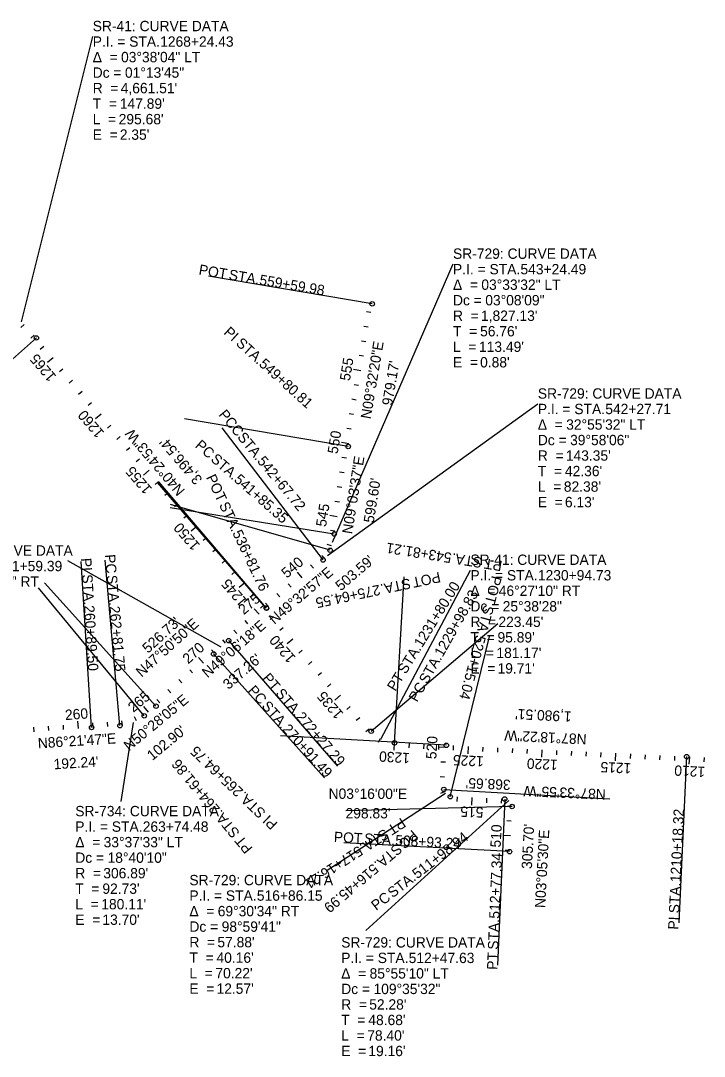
# Model space of a CAD drawing. Extents: x 99589 to 110840, y 526591 to 533644.
# Drawn here: x 102357 to 106985, y 526635 to 533644 of the extents above; entities that cross this region are included whole.
import ezdxf

# ---------------------------------------------------------------- set-up
doc = ezdxf.new("R2010")
doc.units = 0
for name, color, linetype in [('GE_P_Alignment_500_Bearings', 7, 'Continuous'), ('GE_P_Alignment_500_Cardinal_Points', 7, 'Continuous'), ('GE_P_Alignment_500_Curve_Data', 7, 'Continuous'), ('GE_P_Alignment_500_Distances', 7, 'Continuous'), ('GE_P_Alignment_500_Stations', 7, 'Continuous')]:
    doc.layers.add(name, color=color, linetype=linetype)

msp = doc.modelspace()

# ---------------------------------------------------------------- linework, layer by layer
at = {"layer": 'GE_P_Alignment_500_Cardinal_Points'}
for p, q in [((104736.9, 531727.6), (103627.4, 531914)), ((102463.2, 531497.2), (101620.2, 530752.1)), ((104574.6, 530762), (103465.2, 530948.4)), ((104404.3, 529994.3), (103720.9, 530887.8)), ((104019.9, 529668.9), (103283.4, 530519.3)), ((104021.1, 529667.5), (103291.2, 530523.6)), ((104452.2, 530059.9), (103371, 530370.7)), ((104480.2, 530169.9), (103369.2, 530347)), ((102836.9, 528860.6), (102765.5, 529983.3)), ((103028.8, 528872.8), (102928.3, 529993.3)), ((104887.7, 528756.3), (104952.6, 529879.4)), ((103272.8, 529004.6), (102517.8, 529838.6)), ((103193.4, 528939.1), (102477.4, 529806.8)), ((104730, 528835), (105586.6, 529564.4)), ((105265.5, 528391.9), (105534.3, 529484.3)), ((103765, 529448.1), (104501.5, 528597.7)), ((103663.3, 529358.1), (104414.2, 528520.4)), ((105238.8, 528739.8), (104115.7, 528803.9)), ((106866, 528663.2), (106813.1, 527539.4)), ((105221.8, 528441.4), (106345, 528377.3)), ((105633.8, 528376.3), (105586, 527252.3)), ((105683.7, 528325.4), (104559.1, 528295.4)), ((105667.2, 528020.2), (104543.9, 528080.8))]:
    msp.add_line(p, q, dxfattribs=at)
for centre in [(104736.9, 531727.6), (102463.2, 531497.2), (104574.6, 530762), (104480.2, 530169.9), (104452.2, 530059.9), (104404.3, 529994.3), (104019.9, 529668.9), (104021.1, 529667.5), (103765, 529448.1), (103663.3, 529358.1), (103272.8, 529004.6), (103193.4, 528939.1), (102836.9, 528860.6), (103028.8, 528872.8), (104730, 528835), (104887.7, 528756.3), (105238.8, 528739.8), (106866, 528663.2), (105221.8, 528441.4), (105265.5, 528391.9), (105633.8, 528376.3), (105683.7, 528325.4), (105667.2, 528020.2)]:
    msp.add_circle(centre, 15, dxfattribs=at)
at = {"layer": 'GE_P_Alignment_500_Curve_Data'}
for p, q in [((102363.5, 531606.4), (102844.5, 533538)), ((104467.1, 530114.7), (105284, 531997.5)), ((104433.3, 530024.8), (105858.3, 531051.1)), ((103714, 529403.3), (102676.4, 529987.7)), ((104796.1, 528781.9), (105401.9, 529925.8)), ((103118.5, 528894.8), (103035.2, 528360)), ((105233.2, 528414.1), (104425.4, 527888.7)), ((105660.9, 528366), (104694.1, 527486.6))]:
    msp.add_line(p, q, dxfattribs=at)
at = {"layer": 'GE_P_Alignment_500_Stations'}
for p, q in [((104726.9, 531668.5), (104697.3, 531673.4)), ((102380.2, 531588.6), (102358.2, 531568.1)), ((104710.4, 531569.8), (104680.8, 531574.8)), ((102447.6, 531514.7), (102425.2, 531494.7)), ((102512.8, 531438.9), (102489.9, 531419.5)), ((104693.8, 531471.2), (104664.2, 531476.2)), ((102577.6, 531362.8), (102539.5, 531330.4)), ((104677.2, 531372.6), (104647.6, 531377.6)), ((102642.4, 531286.6), (102619.6, 531267.2)), ((104660.6, 531274), (104611.3, 531282.3)), ((102707.3, 531210.5), (102684.4, 531191)), ((104644.1, 531175.4), (104614.5, 531180.3)), ((102772.1, 531134.4), (102749.3, 531114.9)), ((104627.5, 531076.7), (104597.9, 531081.7)), ((102836.9, 531058.2), (102814.1, 531038.8)), ((102901.8, 530982.1), (102863.7, 530949.7)), ((104610.9, 530978.1), (104581.3, 530983.1)), ((102966.6, 530905.9), (102943.8, 530886.5)), ((104594.4, 530879.5), (104564.8, 530884.5)), ((103031.4, 530829.8), (103008.6, 530810.4)), ((103096.3, 530753.7), (103073.4, 530734.2)), ((104577.8, 530780.9), (104528.5, 530789.2)), ((103161.1, 530677.5), (103138.3, 530658.1)), ((104561.9, 530682.2), (104532.3, 530686.9)), ((103225.9, 530601.4), (103187.9, 530569)), ((104546.1, 530583.4), (104516.5, 530588.1)), ((103290.8, 530525.3), (103267.9, 530505.8)), ((103355.6, 530449.1), (103332.7, 530429.7)), ((104530.4, 530484.7), (104500.8, 530489.4)), ((103420.4, 530373), (103397.6, 530353.5)), ((104514.6, 530385.9), (104485, 530390.6)), ((103485.3, 530296.8), (103462.4, 530277.4)), ((104498.9, 530287.2), (104449.5, 530295)), ((103550.1, 530220.7), (103512, 530188.3)), ((104483.1, 530188.4), (104453.5, 530193.1)), ((103614.9, 530144.6), (103592.1, 530125.1)), ((104460.9, 530091), (104431.9, 530098.8)), ((103679.7, 530068.4), (103656.9, 530049)), ((104415.5, 530003.7), (104394.9, 530025.6)), ((103744.6, 529992.3), (103721.7, 529972.8)), ((104339.4, 529938.9), (104319.9, 529961.7)), ((103809.4, 529916.2), (103786.6, 529896.7)), ((104263.3, 529874), (104230.9, 529912.1)), ((103874.2, 529840), (103836.2, 529807.6)), ((104187.2, 529809.1), (104167.7, 529832)), ((103939.1, 529763.9), (103916.2, 529744.4)), ((104111.1, 529744.2), (104091.6, 529767.1)), ((104003.9, 529687.8), (103981.1, 529668.3)), ((104035, 529679.4), (104015.5, 529702.2)), ((103971.1, 529626.7), (103938.4, 529664.4)), ((104068.7, 529611.6), (104045.9, 529592.2)), ((103895.6, 529561.2), (103875.9, 529583.9)), ((104133.6, 529535.5), (104110.7, 529516)), ((103820, 529495.7), (103800.3, 529518.4)), ((104198.4, 529459.3), (104160.3, 529426.9)), ((103744.5, 529430.1), (103724.7, 529452.7)), ((103595.5, 529296.7), (103561.9, 529333.8)), ((103669.6, 529363.8), (103649.6, 529386.2)), ((104263.2, 529383.2), (104240.4, 529363.8)), ((103521.3, 529229.6), (103501.2, 529251.8)), ((104328.1, 529307.1), (104305.2, 529287.6)), ((103447.2, 529162.5), (103427.1, 529184.7)), ((104392.9, 529230.9), (104370.1, 529211.5)), ((103373.1, 529095.4), (103352.9, 529117.6)), ((104457.7, 529154.8), (104434.9, 529135.3)), ((103298.9, 529028.3), (103278.8, 529050.5)), ((104522.6, 529078.7), (104484.5, 529046.2)), ((103222.9, 528963.4), (103191, 529002)), ((104587.4, 529002.5), (104564.5, 528983.1)), ((102747.7, 528854), (102744, 528903.9)), ((102947.2, 528867.6), (102945.3, 528897.6)), ((103046.9, 528875), (103042.4, 528904.6)), ((103141.6, 528905.5), (103127.9, 528932.2)), ((104652.2, 528926.4), (104629.4, 528906.9)), ((102448.5, 528831.9), (102446.3, 528861.8)), ((102548.2, 528839.3), (102546, 528869.2)), ((102647.9, 528846.6), (102645.7, 528876.5)), ((102847.4, 528861.3), (102845.5, 528891.2)), ((104717.1, 528850.2), (104694.2, 528830.8)), ((104791.4, 528784.4), (104776.8, 528758.2)), ((104886.5, 528756.3), (104883.4, 528706.4)), ((104986.4, 528751.6), (104985, 528721.7)), ((105086.3, 528746.9), (105084.9, 528717)), ((105186.2, 528742.2), (105184.8, 528712.3)), ((105238, 528724.7), (105188.1, 528727.6)), ((105286.1, 528737.5), (105284.7, 528707.6)), ((105386, 528732.8), (105383.6, 528682.9)), ((105485.9, 528728.1), (105484.5, 528698.2)), ((105585.8, 528723.4), (105584.4, 528693.5)), ((105685.7, 528718.7), (105684.2, 528688.8)), ((105785.5, 528714), (105784.1, 528684.1)), ((105885.4, 528709.3), (105883.1, 528659.4)), ((105985.3, 528704.6), (105983.9, 528674.7)), ((106085.2, 528699.9), (106083.8, 528670)), ((106185.1, 528695.2), (106183.7, 528665.3)), ((106285, 528690.5), (106283.6, 528660.6)), ((105232.3, 528624.9), (105202.3, 528626.6)), ((106384.9, 528685.8), (106382.5, 528635.9)), ((106484.8, 528681.1), (106483.4, 528651.2)), ((106584.7, 528676.4), (106583.2, 528646.5)), ((106684.5, 528671.7), (106683.1, 528641.8)), ((106784.4, 528667), (106783, 528637.1)), ((106884.3, 528662.2), (106881.7, 528612.3)), ((106984.2, 528657), (106982.6, 528627)), ((105226.6, 528525.1), (105196.6, 528526.8)), ((105225.9, 528425.8), (105198.2, 528414.2)), ((105311.4, 528390), (105310.2, 528360)), ((105411.3, 528385.7), (105409.2, 528335.8)), ((105511.2, 528381.5), (105510, 528351.5)), ((105611.2, 528377.2), (105609.9, 528347.3)), ((105683.7, 528326.5), (105653.7, 528325.1)), ((105678.4, 528226.6), (105648.4, 528228.2)), ((105673, 528126.8), (105623.1, 528129.5)), ((105667.6, 528026.9), (105637.7, 528028.5))]:
    msp.add_line(p, q, dxfattribs=at)

# ---------------------------------------------------------------- texts
at = {"layer": 'GE_P_Alignment_500_Bearings'}
for s, rotation, p in [('N09°32\'20"E', 80.46122, (104727, 530944.8)), ('N40°24\'53"W', 130.41474, (103473.3, 530466)), ('N09°03\'37"E', 80.93973, (104601.2, 530166.5)), ('N49°32\'57"E', 40.45073, (104074.4, 529555.3)), ('N47°50\'50"E', 42.15273, (103175.4, 529197.4)), ('N49°06\'18"E', 40.89492, (103621.8, 529192.8)), ('N50°28\'05"E', 39.53195, (103090.4, 528698.5)), ('N87°18\'22"W', 177.30607, (106190, 528815.1)), ('N86°21\'47"E', 3.63699, (102475, 528719)), ('N03°16\'00"E', 359.85197, (104441.7, 528377.6)), ('N87°33\'55"W', 177.56534, (106319.6, 528441.9)), ('N03°05\'30"E', 86.90826, (105907.7, 527637.4))]:
    msp.add_text(s, height=70, rotation=rotation, dxfattribs=at).set_placement(p)
at = {"layer": 'GE_P_Alignment_500_Cardinal_Points'}
for s, rotation, p in [('POT', 350.46122, (103558.9, 531926.6)), (' STA. ', 350.46122, (103736.4, 531896.8)), ('559+59.98', 350.46122, (103969.4, 531857.6)), ('PI', 317.95547, (103726.9, 531527.9)), (' STA. ', 317.95547, (103789.9, 531471.1)), ('549+80.81', 317.95547, (103965.3, 531312.8)), ('PCC', 309.6937, (103693.4, 530975.8)), ('PC', 318.68084, (103532.9, 530761.7)), (' STA. ', 309.6937, (103803.4, 530843.2)), (' STA. ', 318.68084, (103619, 530686.1)), ('542+67.72', 309.6937, (103954.3, 530661.4)), ('POT', 295.3785, (103609.9, 530553.6)), ('541+85.35', 318.68084, (103796.5, 530530.1)), (' STA. ', 295.3785, (103687, 530391)), ('536+81.76', 295.3785, (103788.3, 530177.5)), ('543+81.21', 170.93973, (105278.5, 530041.5)), ('PC', 275.12547, (102926.1, 530029.5)), (' STA. ', 170.93973, (105511.9, 530004.3)), ('PI', 273.63699, (102765.2, 530005.7)), ('PT', 170.93973, (105620.8, 529986.9)), (' STA. ', 273.63699, (102770.6, 529921.1)), (' STA. ', 275.12547, (102936.3, 529915.3)), ('POT', 191.94192, (105191.2, 529913.9)), ('POT', 255.05541, (105547.5, 529892.2)), ('275+64.55', 191.94192, (104783.9, 529827.8)), (' STA. ', 191.94192, (105015.1, 529876.7)), ('1231+80.00', 58.3886, (105074.3, 529396.4)), ('1229+98.83', 60.45546, (105213.5, 529333.2)), ('260+89.50', 273.63699, (102785.5, 529685.3)), ('262+81.75', 275.12547, (102957.4, 529680)), (' STA. ', 255.05541, (105501.1, 529718.3)), ('520+15.04', 255.05541, (105440.2, 529490)), (' STA. ', 58.3886, (104950.5, 529195.2)), (' STA. ', 60.45546, (105097, 529127.7)), ('PT', 310.89492, (103988.7, 529191.4)), ('PT', 58.3886, (104892.6, 529101.2)), ('PC', 311.87124, (103890, 529106.8)), (' STA. ', 310.89492, (104061, 529108)), ('PC', 60.45546, (105040.5, 529027.9)), (' STA. ', 311.87124, (103966.5, 529021.5)), ('272+27.29', 310.89492, (104215.7, 528929.3)), ('270+91.49', 311.87124, (104124.2, 528845.5)), ('265+64.75', 136.35225, (103869.2, 528434.3)), ('264+61.86', 129.53195, (103710.6, 528310.8)), (' STA. ', 136.35225, (104040.2, 528271.2)), (' STA. ', 129.53195, (103861, 528128.6)), ('PI', 136.35225, (104101.5, 528212.7)), ('1210+18.32', 87.30607, (106824.9, 527811.7)), ('PT', 213.07385, (104933.5, 528252.4)), ('POT', 356.90826, (104475.9, 528085.6)), (' STA. ', 213.07385, (104841, 528192.2)), (' STA. ', 356.90826, (104655.7, 528075.9)), ('508+93.24', 356.90826, (104891.6, 528063.1)), ('PC', 220.51366, (105008.9, 528171.3)), ('511+98.94', 37.60884, (105041.8, 527832.3)), ('PT', 129.53195, (103931.3, 528043.4)), (' STA. ', 220.51366, (104921.7, 528096.8)), ('517+16.21', 213.07385, (104643, 528063.2)), ('512+77.34', 87.56534, (105598.3, 527565.4)), ('516+45.99', 220.51366, (104742.1, 527943.3)), (' STA. ', 37.60884, (104854.6, 527688.1)), (' STA. ', 87.30607, (106813.8, 527575.6)), ('PC', 37.60884, (104763.8, 527618.1)), ('PI', 87.30607, (106809.8, 527490.9)), (' STA. ', 87.56534, (105588.2, 527329.3)), ('PT', 87.56534, (105583.5, 527219.1))]:
    msp.add_text(s, height=70, rotation=rotation, dxfattribs=at).set_placement(p)
at = {"layer": 'GE_P_Alignment_500_Curve_Data'}
for s, p in [('SR-41: CURVE DATA', (102844.5, 533573)), ('P.I. = STA. ', (102844.5, 533468)), ('1268+24.43', (103301.2, 533468)), ('Δ  = ', (102844.5, 533363)), ('03°38\'04" LT', (103036.4, 533363)), ('Dc = ', (102844.5, 533258)), ('01°13\'45"', (103063, 533258)), ('R  = ', (102844.5, 533153)), ("4,661.51'", (103034.1, 533153)), ('T  = ', (102844.5, 533048)), ("147.89'", (103028, 533048)), ('L  = ', (102844.5, 532943)), ("295.68'", (103020.5, 532943)), ('E  = ', (102844.5, 532838)), ("2.35'", (103028, 532838)), ('SR-729: CURVE DATA', (105284, 532032.5)), ('P.I. = STA. ', (105284, 531927.5)), ('543+24.49', (105740.7, 531927.5)), ('Δ  = ', (105284, 531822.5)), ('03°33\'32" LT', (105475.9, 531822.5)), ('Dc = ', (105284, 531717.5)), ('03°08\'09"', (105502.5, 531717.5)), ('R  = ', (105284, 531612.5)), ("1,827.13'", (105473.6, 531612.5)), ('T  = ', (105284, 531507.5)), ("56.76'", (105467.4, 531507.5)), ('L  = ', (105284, 531402.5)), ("113.49'", (105460, 531402.5)), ('E  = ', (105284, 531297.5)), ("0.88'", (105467.5, 531297.5)), ('SR-729: CURVE DATA', (105858.3, 531086.1)), ('P.I. = STA. ', (105858.3, 530981.1)), ('542+27.71', (106315, 530981.1)), ('Δ  = ', (105858.3, 530876.1)), ('32°55\'32" LT', (106050.2, 530876.1)), ('Dc = ', (105858.3, 530771.1)), ('39°58\'06"', (106076.8, 530771.1)), ('R  = ', (105858.3, 530666.1)), ("143.35'", (106047.8, 530666.1)), ('T  = ', (105858.3, 530561.1)), ("42.36'", (106041.7, 530561.1)), ('L  = ', (105858.3, 530456.1)), ("82.38'", (106034.3, 530456.1)), ('E  = ', (105858.3, 530351.1)), ("6.13'", (106041.8, 530351.1)), ('SR-734: CURVE DATA', (101736.7, 530023.3)), ('SR-41: CURVE DATA', (105401.9, 529960.8)), ('271+59.39', (102193.3, 529918.3)), ('00°43\'36" RT', (101928.6, 529813.3)), ('P.I. = STA. ', (105401.9, 529855.8)), ('1230+94.73', (105858.6, 529855.8)), ('Δ  = ', (105401.9, 529750.8)), ('46°27\'10" RT', (105593.8, 529750.8)), ('Dc = ', (105401.9, 529645.8)), ('25°38\'28"', (105620.4, 529645.8)), ('R  = ', (105401.9, 529540.8)), ("223.45'", (105591.4, 529540.8)), ('T  = ', (105401.9, 529435.8)), ("95.89'", (105585.3, 529435.8)), ('L  = ', (105401.9, 529330.8)), ("181.17'", (105577.9, 529330.8)), ('E  = ', (105401.9, 529225.8)), ("19.71'", (105585.4, 529225.8)), ('SR-734: CURVE DATA', (102726.6, 528259.6)), ('P.I. = STA. ', (102726.6, 528154.6)), ('263+74.48', (103183.3, 528154.6)), ('Δ  = ', (102726.6, 528049.6)), ('33°37\'33" LT', (102918.5, 528049.6)), ('Dc = ', (102726.6, 527944.6)), ('18°40\'10"', (102945.1, 527944.6)), ('R  = ', (102726.6, 527839.6)), ("306.89'", (102916.2, 527839.6)), ('SR-729: CURVE DATA', (103499.2, 527792.8)), ('T  = ', (102726.6, 527734.6)), ("92.73'", (102910.1, 527734.6)), ('P.I. = STA. ', (103499.2, 527687.8)), ('516+86.15', (103955.8, 527687.8)), ('L  = ', (102726.6, 527629.6)), ("180.11'", (102902.6, 527629.6)), ('Δ  = ', (103499.2, 527582.8)), ('69°30\'34" RT', (103691.1, 527582.8)), ('E  = ', (102726.6, 527524.6)), ("13.70'", (102910.1, 527524.6)), ('Dc = ', (103499.2, 527477.8)), ('98°59\'41"', (103717.6, 527477.8)), ('R  = ', (103499.2, 527372.8)), ("57.88'", (103688.7, 527372.8)), ('SR-729: CURVE DATA', (104527.2, 527371.1)), ('T  = ', (103499.2, 527267.8)), ("40.16'", (103682.6, 527267.8)), ('P.I. = STA. ', (104527.2, 527266.1)), ('512+47.63', (104983.9, 527266.1)), ('L  = ', (103499.2, 527162.8)), ("70.22'", (103675.2, 527162.8)), ('Δ  = ', (104527.2, 527161.1)), ('85°55\'10" LT', (104719.2, 527161.1)), ('E  = ', (103499.2, 527057.8)), ("12.57'", (103682.7, 527057.8)), ('Dc = ', (104527.2, 527056.1)), ('109°35\'32"', (104745.7, 527056.1)), ('R  = ', (104527.2, 526951.1)), ("52.28'", (104716.8, 526951.1)), ('T  = ', (104527.2, 526846.1)), ("48.68'", (104710.7, 526846.1)), ('L  = ', (104527.2, 526741.1)), ("78.40'", (104703.3, 526741.1)), ('E  = ', (104527.2, 526636.1)), ("19.16'", (104710.7, 526636.1))]:
    msp.add_text(s, height=70, dxfattribs=at).set_placement(p)
at = {"layer": 'GE_P_Alignment_500_Distances'}
for s, rotation, p in [("979.17'", 80.46122, (104871.5, 531035.3)), ("3,496.54'", 130.41474, (103591.3, 530541.4)), ("599.60'", 80.93973, (104746.9, 530241.6)), ("503.59'", 40.45073, (104524.8, 529781.2)), ("526.73'", 42.15273, (103219, 529358.9)), ("337.26'", 40.89492, (103763.6, 529113.7)), ("1,980.51'", 177.30607, (106088.5, 528968.6)), ("102.90'", 39.53195, (103248, 528633)), ("192.24'", 3.63699, (102582.2, 528576.8)), ("368.65'", 177.56534, (105675.7, 528506.5)), ("298.83'", 0.06893, (104556.4, 528244.9)), ("305.70'", 86.90826, (105817.9, 527901.5))]:
    msp.add_text(s, height=70, rotation=rotation, dxfattribs=at).set_placement(p)
at = {"layer": 'GE_P_Alignment_500_Stations'}
for s, rotation, p in [('1265', 130.41474, (102601.7, 531238.1)), ('555', 80.46122, (104585.3, 531202.9)), ('1260', 130.41474, (102926.5, 530856.6)), ('550', 80.46122, (104502.3, 530708.7)), ('1255', 130.41474, (103250, 530476.7)), ('545', 80.93973, (104424.2, 530215.4)), ('1250', 130.41474, (103574.9, 530095.2)), ('540', 40.45073, (104159.1, 529867.3)), ('1245', 130.41474, (103898.3, 529715.3)), ('275', 40.89492, (103867.8, 529619.8)), ('1240', 130.41474, (104223.2, 529333.8)), ('270', 42.15273, (103491.5, 529286.9)), ('265', 39.53195, (103119.4, 528959)), ('1235', 130.41474, (104546.6, 528954)), ('260', 4.22925, (102659.6, 528910.2)), ('520', 86.73341, (105170.8, 528644.8)), ('1230', 176.39302, (104994, 528687)), ('1225', 177.30607, (105493.5, 528665.2)), ('1220', 177.30607, (105994, 528641.7)), ('1215', 177.30607, (106492.4, 528618.2)), ('1210', 176.98902, (106992.5, 528594)), ('515', 177.56534, (105491.2, 528319.8)), ('510', 86.90826, (105606.1, 528046.6))]:
    msp.add_text(s, height=70, rotation=rotation, dxfattribs=at).set_placement(p)

doc.saveas('drawing.dxf')
